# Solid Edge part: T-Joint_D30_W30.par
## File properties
Author: hStrempfl
Template: iso metric part.par
Last saved by: fknapp
Revision: 124
Application: Solid Edge
Username: hStrempfl
Genauigkeit: 0,990
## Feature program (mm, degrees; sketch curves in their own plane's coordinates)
sketch for "unnamed Protrusion 1" plane through (0, 0, 0) normal (0, 0, 1) x-axis (1, 0, 0)
  line (14.8, 16.8695) -> (-15, 16.8695)
  line (-15, 16.8695) -> (-15, -12.9305)
  line (-15, -12.9305) -> (14.8, -12.9305)
  line (14.8, -12.9305) -> (14.8, 16.8695)
  dimension (linear) = 15
  dimension (linear) = 14.8
extrude "unnamed Protrusion 1" add finite 16 along +normal
chamfer "Fase_2" setback 15.2  SetBackValue2 = 30 deg
sketch for "Bohrung_1" plane through (0, -10.238, 5.4634) normal (0, -0.866025, 0.5) x-axis (1, 0, 0)
  hole centre (-0.1, 3.9224) bore radius 5.25
hole "Bohrung_1" diameter 10.5 through  CounterSinkAngle = 90 deg
fillet "Verrundung_2" radius 14.9
sketch for "Bohrung_2" plane through (-0.1, 6.1215, 16) normal (0, 0, 1) x-axis (1, 0, 0)
hole "Bohrung_2" diameter 6.2 through  CounterSinkAngle = 90 deg
sketch for "unnamed Hole 1" plane through (-0.1, 6.1215, 16) normal (0, 0, 1) x-axis (1, 0, 0)
hole "unnamed Hole 1" through
pattern "unnamed Pattern 1" of "Bohrung_2", "unnamed Hole 1"
fillet "Verrundung_4" radius 1
fillet "Verrundung_5" radius 0.6
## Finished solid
Body 1: solid body, 12 faces, 26 edges, 14 vertices.
  Faces by surface: cylinder 4, cone 3, plane 3, torus 2
  Edges by curve: circle 14, intersection 7, ellipse 3, line 2
Bounding box of the edges (mm; curved faces can reach further): 29.800 x 29.785 x 16.000, from (-15, -12.9155, 0) to (14.8, 16.8695, 16).
Cylindrical faces by radius (mm): R3.1 x2, R5.25 x1, R14.9 x1
Conical faces (half-angle, radius in mm at the cone's reference point): 45 deg R6 x2, 45 deg R9 x1
Toroidal faces (ring radius, tube radius in mm): R13.9 r1 x1, R14.3 r0.6 x1
Planar faces by outward normal: +z 1, -z 1, oblique 1
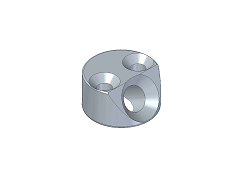
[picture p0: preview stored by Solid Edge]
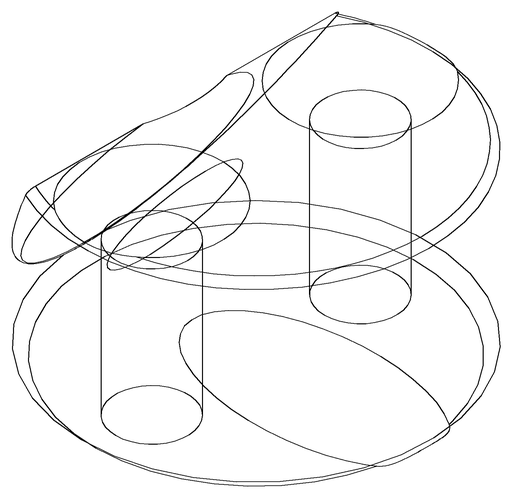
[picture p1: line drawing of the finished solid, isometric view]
